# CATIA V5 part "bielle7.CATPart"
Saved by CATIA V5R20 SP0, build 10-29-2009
Part number: bielle7
Bounding box of the stored display mesh (mm): x 0 to 5, y -10 to 227.988, z -54.992 to 9.998
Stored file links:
  C:\Users\thinkmotion1\Desktop\IAO OK\IAO_2010_1458_splanchena\Correction_Khaled\bielle7.CATPart
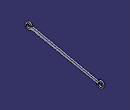
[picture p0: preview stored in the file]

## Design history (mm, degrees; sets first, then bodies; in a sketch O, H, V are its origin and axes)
Body1 (main body)
  Sketch1 on yz-plane, origin (0, 0, 0), H (0, 1, 0), V (0, 0, 1)
    arc A1 centre (0, 0) radius 10 from (9.6617, 2.5791) to (7.9188, -6.1068) ccw
    arc A2 centre (218, -45) radius 10 from (208.0812, -46.2719) to (209.3397, -40) ccw
    line L1 (208.0812, -46.2719) -> (7.9188, -6.1068)
    line L2 (9.6617, 2.5791) -> (209.3397, -40)
    circle A3 centre (0, 0) radius 6
    point P6 (0, -6)
    circle A4 centre (218, -45) radius 6
    radius A3 = 6
    radius A4 = 6
    coincidence: A3 P6, P6 V
  Pad1: profile Sketch1, direction (1, 0, 0), length 5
